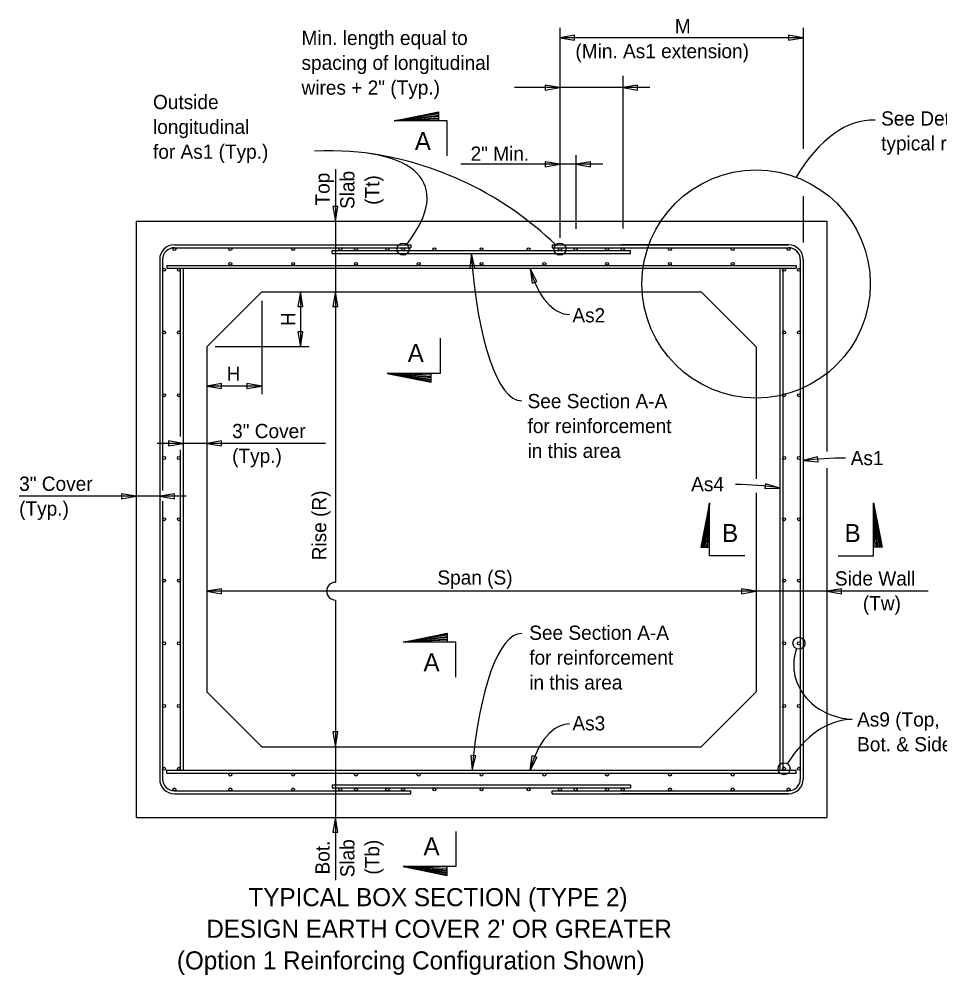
# Model space of a CAD drawing. Extents: x 10340.6 to 10393.7, y 76372.2 to 76398.3.
# Drawn here: x 10340.77 to 10350.54, y 76386.17 to 76396.32 of the extents above; entities that cross this region are included whole.
import ezdxf

# ---------------------------------------------------------------- set-up
doc = ezdxf.new("R2010")
doc.units = 0
for name, color, linetype in [('AdhocPoint_dp', 7, 'Continuous'), ('Patterning', 7, 'Continuous'), ('PlotBorder_dp', 7, 'Continuous'), ('TextMisc', 7, 'Continuous')]:
    doc.layers.add(name, color=color, linetype=linetype)

msp = doc.modelspace()

# ---------------------------------------------------------------- linework, layer by layer
at = {"layer": 'AdhocPoint_dp'}
for p, q in [((10346.51, 76396.23), (10346.51, 76394.001)), ((10349.093, 76396.23), (10349.093, 76394.945)), ((10349.093, 76396.125), (10346.51, 76396.125)), ((10347.177, 76395.722), (10347.177, 76394.098)), ((10346.51, 76395.597), (10346.029, 76395.597)), ((10347.177, 76395.597), (10346.51, 76395.597)), ((10347.464, 76395.597), (10347.177, 76395.597)), ((10344.751, 76395.245), (10345.22, 76395.327)), ((10345.22, 76395.317), (10344.751, 76395.245)), ((10344.751, 76395.245), (10345.22, 76395.305)), ((10345.22, 76395.291), (10344.751, 76395.245)), ((10344.751, 76395.245), (10345.22, 76395.277)), ((10345.22, 76395.262), (10344.751, 76395.245)), ((10346.677, 76394.88), (10346.677, 76394.095)), ((10346.51, 76394.782), (10345.459, 76394.782)), ((10346.677, 76394.782), (10346.51, 76394.782)), ((10346.964, 76394.782), (10346.677, 76394.782)), ((10344.126, 76394.73), (10344.126, 76394.177)), ((10349.093, 76394.442), (10349.093, 76393.95)), ((10344.126, 76394.177), (10344.126, 76393.427)), ((10343.755, 76393.427), (10343.755, 76392.843)), ((10344.126, 76393.427), (10344.126, 76390.34)), ((10343.343, 76393.332), (10343.343, 76392.34)), ((10343.846, 76392.843), (10342.849, 76392.843)), ((10345.144, 76392.542), (10344.675, 76392.559)), ((10344.675, 76392.559), (10345.144, 76392.527)), ((10345.144, 76392.513), (10344.675, 76392.559)), ((10344.675, 76392.559), (10345.144, 76392.499)), ((10345.144, 76392.487), (10344.675, 76392.559)), ((10344.675, 76392.559), (10345.144, 76392.477)), ((10343.343, 76392.426), (10342.76, 76392.426)), ((10342.51, 76391.815), (10342.233, 76391.815)), ((10342.76, 76391.815), (10342.51, 76391.815)), ((10344.02, 76391.815), (10342.76, 76391.815)), ((10342.01, 76391.254), (10340.768, 76391.254)), ((10342.26, 76391.254), (10342.01, 76391.254)), ((10342.541, 76391.254), (10342.26, 76391.254)), ((10348.099, 76391.183), (10348.016, 76390.715)), ((10348.026, 76390.715), (10348.099, 76391.183)), ((10348.099, 76391.183), (10348.039, 76390.715)), ((10348.052, 76390.715), (10348.099, 76391.183)), ((10348.099, 76391.183), (10348.066, 76390.715)), ((10348.081, 76390.715), (10348.099, 76391.183)), ((10349.856, 76390.715), (10349.838, 76391.183)), ((10349.838, 76391.183), (10349.871, 76390.715)), ((10349.885, 76390.715), (10349.838, 76391.183)), ((10349.838, 76391.183), (10349.898, 76390.715)), ((10349.911, 76390.715), (10349.838, 76391.183)), ((10349.838, 76391.183), (10349.921, 76390.715)), ((10348.594, 76390.246), (10342.76, 76390.246)), ((10349.343, 76390.246), (10348.594, 76390.246)), ((10350.421, 76390.246), (10349.343, 76390.246)), ((10344.126, 76390.152), (10344.126, 76388.593)), ((10344.844, 76389.706), (10345.312, 76389.789)), ((10345.312, 76389.779), (10344.844, 76389.706)), ((10344.844, 76389.706), (10345.312, 76389.766)), ((10345.312, 76389.753), (10344.844, 76389.706)), ((10344.844, 76389.706), (10345.312, 76389.739)), ((10345.312, 76389.724), (10344.844, 76389.706)), ((10344.126, 76388.593), (10344.126, 76387.843)), ((10344.126, 76387.843), (10344.126, 76387.177)), ((10345.312, 76387.301), (10344.844, 76387.319)), ((10344.844, 76387.319), (10345.312, 76387.286)), ((10345.312, 76387.272), (10344.844, 76387.319)), ((10344.844, 76387.319), (10345.312, 76387.259)), ((10345.312, 76387.246), (10344.844, 76387.319)), ((10344.844, 76387.319), (10345.312, 76387.236))]:
    msp.add_line(p, q, dxfattribs=at)
for points in [[(10346.51, 76396.125), (10346.666, 76396.099), (10346.666, 76396.152)], [(10349.093, 76396.125), (10348.937, 76396.152), (10348.937, 76396.099)], [(10346.51, 76395.597), (10346.354, 76395.624), (10346.354, 76395.571)], [(10347.177, 76395.597), (10347.333, 76395.571), (10347.333, 76395.624)], [(10346.51, 76394.782), (10346.354, 76394.808), (10346.354, 76394.755)], [(10346.677, 76394.782), (10346.833, 76394.755), (10346.833, 76394.808)], [(10344.126, 76394.177), (10344.153, 76394.333), (10344.1, 76394.333)], [(10345.569, 76393.833), (10345.553, 76393.675), (10345.606, 76393.679)], [(10346.192, 76393.677), (10346.216, 76393.52), (10346.266, 76393.537)], [(10343.755, 76393.427), (10343.728, 76393.271), (10343.781, 76393.271)], [(10344.126, 76393.427), (10344.1, 76393.271), (10344.153, 76393.271)], [(10343.755, 76392.843), (10343.781, 76393), (10343.728, 76393)], [(10342.76, 76392.426), (10342.916, 76392.4), (10342.916, 76392.453)], [(10343.343, 76392.426), (10343.187, 76392.453), (10343.187, 76392.4)], [(10342.51, 76391.815), (10342.354, 76391.842), (10342.354, 76391.789)], [(10342.76, 76391.815), (10342.916, 76391.789), (10342.916, 76391.842)], [(10349.093, 76391.633), (10349.251, 76391.622), (10349.246, 76391.675)], [(10348.844, 76391.341), (10348.692, 76391.388), (10348.685, 76391.336)], [(10342.01, 76391.254), (10341.854, 76391.28), (10341.854, 76391.227)], [(10342.26, 76391.254), (10342.416, 76391.227), (10342.416, 76391.28)], [(10342.76, 76390.246), (10342.916, 76390.219), (10342.916, 76390.272)], [(10348.594, 76390.246), (10348.437, 76390.272), (10348.437, 76390.219)], [(10349.343, 76390.246), (10349.5, 76390.219), (10349.5, 76390.272)], [(10344.126, 76388.593), (10344.153, 76388.75), (10344.1, 76388.75)], [(10345.577, 76388.343), (10345.617, 76388.497), (10345.564, 76388.501)], [(10346.192, 76388.343), (10346.216, 76388.5), (10346.266, 76388.483)], [(10344.126, 76387.843), (10344.1, 76387.687), (10344.153, 76387.687)]]:
    msp.add_lwpolyline(points, close=True, dxfattribs=at)
for points in [[(10345.314, 76394.87), (10345.314, 76395.245), (10344.751, 76395.245), (10345.22, 76395.338), (10345.22, 76395.245)], [(10345.237, 76392.934), (10345.237, 76392.559), (10344.675, 76392.559), (10345.144, 76392.466), (10345.144, 76392.559)], [(10348.474, 76390.621), (10348.099, 76390.621), (10348.099, 76391.183), (10348.005, 76390.715), (10348.099, 76390.715)], [(10349.463, 76390.621), (10349.838, 76390.621), (10349.838, 76391.183), (10349.932, 76390.715), (10349.838, 76390.715)], [(10345.406, 76389.331), (10345.406, 76389.706), (10344.844, 76389.706), (10345.312, 76389.8), (10345.312, 76389.706)], [(10345.406, 76387.694), (10345.406, 76387.319), (10344.844, 76387.319), (10345.312, 76387.225), (10345.312, 76387.319)]]:
    msp.add_lwpolyline(points, dxfattribs=at)
for centre, radius in [((10348.593, 76393.51), 1.212), ((10344.844, 76393.88), 0.0638), ((10346.51, 76393.88), 0.0638), ((10349.047, 76389.692), 0.0638), ((10348.89, 76388.359), 0.0638)]:
    msp.add_circle(centre, radius, dxfattribs=at)
for centre, radius, start, end in [((10343.972, 76391.35), 3.584, 45.9281, 82.489), ((10349.501, 76388.443), 3.216, 89.2818, 97.2882), ((10348.41, 76388.825), 2.553, 80.213, 90.7866), ((10344.126, 76390.246), 0.0939, 90, 270)]:
    msp.add_arc(centre, radius, start, end, dxfattribs=at)
for centre, major_axis, ratio, start_param, end_param in [((10349.746, 76392.49), (-0.109, -2.761), 0.461067, 3.141593, 3.834554), ((10341.341, 76393.088), (-3.733, -1.474), 0.29335, 2.685849, 3.846834), ((10346.111, 76394.362), (0.007, 2.095), 0.266639, 1.826771, 3.141593), ((10346.624, 76394.144), (-0.012, -0.959), 0.511154, 5.227094, 6.283185), ((10346.111, 76387.702), (0.007, -2.095), 0.266639, 3.141593, 4.400334), ((10349.64, 76389.454), (-0.648, 0.03), 0.879421, 6.015626, 7.853982), ((10346.624, 76387.877), (-0.012, 0.959), 0.511154, 0, 1.056091), ((10349.633, 76386.881), (0.019, -2.003), 0.541712, 3.141593, 3.836225)]:
    msp.add_ellipse(centre, major_axis=major_axis, ratio=ratio, start_param=start_param, end_param=end_param, dxfattribs=at)
at = {"layer": 'Patterning'}
for p, q in [((10342.01, 76394.177), (10342.01, 76387.843)), ((10342.01, 76394.177), (10349.343, 76394.177)), ((10349.343, 76394.177), (10349.343, 76391.731)), ((10343.343, 76393.427), (10342.76, 76392.843)), ((10343.343, 76393.427), (10348.01, 76393.427)), ((10348.594, 76392.843), (10348.01, 76393.427)), ((10342.76, 76392.843), (10342.76, 76389.177)), ((10348.594, 76392.843), (10348.594, 76391.441)), ((10349.343, 76391.554), (10349.343, 76387.843)), ((10348.594, 76391.292), (10348.594, 76389.177)), ((10342.76, 76389.177), (10343.343, 76388.593)), ((10348.01, 76388.593), (10348.594, 76389.177)), ((10343.343, 76388.593), (10348.01, 76388.593)), ((10342.01, 76387.843), (10349.343, 76387.843))]:
    msp.add_line(p, q, dxfattribs=at)
at = {"layer": 'PlotBorder_dp'}
for p, q in [((10342.416, 76393.927), (10344.192, 76393.927)), ((10342.416, 76393.895), (10344.927, 76393.895)), ((10344.01, 76393.927), (10344.927, 76393.927)), ((10344.093, 76393.864), (10347.26, 76393.864)), ((10344.093, 76393.833), (10344.093, 76393.864)), ((10344.927, 76393.927), (10344.927, 76393.895)), ((10346.427, 76393.927), (10346.427, 76393.895)), ((10346.427, 76393.927), (10348.937, 76393.927)), ((10346.427, 76393.895), (10348.937, 76393.895)), ((10348.937, 76393.927), (10347.161, 76393.927)), ((10347.26, 76393.833), (10347.26, 76393.864)), ((10342.26, 76393.77), (10342.26, 76388.25)), ((10342.291, 76393.77), (10342.291, 76391.317)), ((10344.093, 76393.833), (10347.26, 76393.833)), ((10349.062, 76393.77), (10349.062, 76388.25)), ((10349.093, 76393.77), (10349.093, 76388.25)), ((10342.336, 76393.708), (10349.018, 76393.708)), ((10342.336, 76393.708), (10342.336, 76393.677)), ((10342.336, 76393.677), (10349.018, 76393.677)), ((10342.479, 76393.677), (10342.479, 76391.888)), ((10342.51, 76393.677), (10342.51, 76388.343)), ((10348.844, 76393.677), (10348.844, 76388.343)), ((10348.875, 76393.677), (10348.875, 76388.343)), ((10349.018, 76393.708), (10349.018, 76393.677)), ((10342.479, 76391.748), (10342.479, 76388.343)), ((10342.291, 76391.201), (10342.291, 76388.25)), ((10342.336, 76388.343), (10349.018, 76388.343)), ((10342.336, 76388.312), (10342.336, 76388.343)), ((10342.336, 76388.312), (10349.018, 76388.312)), ((10349.018, 76388.312), (10349.018, 76388.343)), ((10344.093, 76388.187), (10344.093, 76388.156)), ((10344.093, 76388.187), (10347.26, 76388.187)), ((10347.26, 76388.187), (10347.26, 76388.156)), ((10342.416, 76388.125), (10344.927, 76388.125)), ((10342.416, 76388.093), (10344.192, 76388.093)), ((10344.01, 76388.093), (10344.927, 76388.093)), ((10344.093, 76388.156), (10347.26, 76388.156)), ((10344.927, 76388.093), (10344.927, 76388.125)), ((10346.427, 76388.093), (10346.427, 76388.125)), ((10346.427, 76388.125), (10348.937, 76388.125)), ((10346.427, 76388.093), (10348.937, 76388.093)), ((10348.937, 76388.093), (10347.161, 76388.093))]:
    msp.add_line(p, q, dxfattribs=at)
for centre in [(10342.416, 76393.88), (10343.01, 76393.88), (10343.01, 76393.88), (10343.677, 76393.88), (10344.177, 76393.88), (10344.343, 76393.88), (10344.343, 76393.88), (10344.677, 76393.88), (10344.844, 76393.88), (10345.177, 76393.88), (10345.677, 76393.88), (10345.677, 76393.88), (10346.177, 76393.88), (10346.51, 76393.88), (10346.677, 76393.88), (10347.01, 76393.88), (10347.01, 76393.88), (10347.177, 76393.88), (10347.677, 76393.88), (10348.344, 76393.88), (10348.344, 76393.88), (10348.937, 76393.88), (10342.307, 76393.661), (10342.463, 76393.661), (10343.01, 76393.724), (10343.677, 76393.724), (10344.343, 76393.724), (10345.01, 76393.724), (10345.677, 76393.724), (10346.344, 76393.724), (10347.01, 76393.724), (10347.677, 76393.724), (10348.344, 76393.724), (10348.89, 76393.661), (10349.047, 76393.661), (10342.307, 76392.995), (10342.463, 76392.995), (10348.89, 76392.995), (10349.047, 76392.995), (10342.307, 76392.328), (10342.463, 76392.328), (10348.89, 76392.328), (10349.047, 76392.328), (10342.307, 76391.661), (10342.463, 76391.661), (10348.89, 76391.661), (10349.047, 76391.661), (10342.307, 76391.01), (10342.463, 76391.01), (10348.89, 76391.01), (10349.047, 76391.01), (10342.307, 76390.359), (10342.463, 76390.359), (10348.89, 76390.359), (10349.047, 76390.359), (10342.307, 76389.692), (10342.463, 76389.692), (10348.89, 76389.692), (10349.047, 76389.692), (10342.307, 76389.026), (10342.463, 76389.026), (10348.89, 76389.026), (10349.047, 76389.026), (10342.307, 76388.359), (10342.463, 76388.359), (10343.01, 76388.297), (10343.677, 76388.297), (10344.343, 76388.297), (10345.01, 76388.297), (10345.677, 76388.297), (10346.344, 76388.297), (10347.01, 76388.297), (10347.677, 76388.297), (10348.344, 76388.297), (10348.89, 76388.359), (10349.047, 76388.359), (10342.416, 76388.14), (10343.01, 76388.14), (10343.01, 76388.14), (10343.677, 76388.14), (10344.177, 76388.14), (10344.343, 76388.14), (10344.343, 76388.14), (10344.677, 76388.14), (10344.844, 76388.14), (10345.177, 76388.14), (10345.677, 76388.14), (10345.677, 76388.14), (10346.177, 76388.14), (10346.51, 76388.14), (10346.677, 76388.14), (10347.01, 76388.14), (10347.01, 76388.14), (10347.177, 76388.14), (10347.677, 76388.14), (10348.344, 76388.14), (10348.344, 76388.14), (10348.937, 76388.14)]:
    msp.add_circle(centre, 0.0156, dxfattribs=at)
for centre, radius, start, end in [((10342.416, 76393.77), 0.156, 89.9999, 179.9999), ((10342.416, 76393.77), 0.125, 90, 180), ((10348.937, 76393.77), 0.156, 0.0001, 90.0001), ((10348.937, 76393.77), 0.125, 0, 90), ((10342.416, 76388.25), 0.156, 180.0001, 270.0001), ((10342.416, 76388.25), 0.125, 180, 270), ((10348.937, 76388.25), 0.125, 270, 0), ((10348.937, 76388.25), 0.156, 269.9999, 359.9999)]:
    msp.add_arc(centre, radius, start, end, dxfattribs=at)

# ---------------------------------------------------------------- texts
at = {"layer": 'AdhocPoint_dp'}
for s, height, p in [('M', 0.151, (10347.73, 76396.173)), ('Min. length equal to', 0.1512, (10343.766, 76396.049)), ('(Min. As1 extension)', 0.1512, (10346.674, 76395.909)), ('spacing of longitudinal', 0.1512, (10343.766, 76395.785)), ('wires + 2" (Typ.)', 0.1512, (10343.766, 76395.521)), ('Outside', 0.1512, (10342.189, 76395.368)), ('See Detail "A" for', 0.1512, (10349.92, 76395.193)), ('longitudinal', 0.1512, (10342.189, 76395.104)), ('typical reinforcing', 0.1512, (10349.92, 76394.929)), ('for As1 (Typ.)', 0.1512, (10342.189, 76394.84)), ('See Section A-A', 0.1512, (10346.166, 76392.19)), ('for reinforcement', 0.1512, (10346.166, 76391.926)), ('3" Cover', 0.1512, (10343.029, 76391.872)), ('(Typ.)', 0.1512, (10343.029, 76391.608)), ('in this area', 0.1512, (10346.166, 76391.662)), ('3" Cover', 0.1512, (10340.768, 76391.312)), ('(Typ.)', 0.1512, (10340.768, 76391.048)), ('Side Wall', 0.1512, (10349.429, 76390.306)), ('(Tw)', 0.1512, (10349.726, 76390.042)), ('See Section A-A', 0.1512, (10346.184, 76389.729)), ('for reinforcement', 0.1512, (10346.184, 76389.465)), ('in this area', 0.1512, (10346.184, 76389.201)), ('As9 (Top,', 0.1512, (10349.665, 76388.808)), ('Bot. & Sides)', 0.1512, (10349.665, 76388.544)), ('TYPICAL BOX SECTION (TYPE 2)', 0.192, (10343.204, 76386.899)), ("DESIGN EARTH COVER 2' OR GREATER", 0.192, (10342.755, 76386.563)), ('(Option 1 Reinforcing Configuration Shown)', 0.192, (10342.443, 76386.227))]:
    msp.add_text(s, height=height, dxfattribs=at).set_placement(p)
for s, p in [('Top', (10344.064, 76394.344)), ('Slab', (10344.328, 76394.307)), ('(Tt)', (10344.592, 76394.351)), ('Bot.', (10344.064, 76387.236)), ('Slab', (10344.328, 76387.206)), ('(Tb)', (10344.592, 76387.234))]:
    msp.add_text(s, height=0.1512, rotation=90, dxfattribs=at).set_placement(p)
at = {"layer": 'TextMisc'}
for s, height, p in [('A', 0.192, (10344.969, 76394.932)), ('2" Min.', 0.1512, (10345.561, 76394.819)), ('As2', 0.1512, (10346.642, 76393.102)), ('A', 0.192, (10344.893, 76392.68)), ('H', 0.151, (10342.971, 76392.481)), ('As1', 0.1512, (10349.597, 76391.585)), ('As4', 0.1512, (10347.903, 76391.308)), ('B', 0.192, (10348.231, 76390.768)), ('B', 0.192, (10349.532, 76390.768)), ('Span (S)', 0.1512, (10345.209, 76390.316)), ('A', 0.192, (10345.061, 76389.394)), ('As3', 0.1512, (10346.642, 76388.767)), ('A', 0.192, (10345.061, 76387.439))]:
    msp.add_text(s, height=height, dxfattribs=at).set_placement(p)
for s, height, p in [('H', 0.151, (10343.699, 76393.063)), ('Rise (R)', 0.1512, (10344.029, 76390.574))]:
    msp.add_text(s, height=height, rotation=90, dxfattribs=at).set_placement(p)

doc.saveas('drawing.dxf')
